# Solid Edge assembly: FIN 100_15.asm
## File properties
Title: Zylinder
Author: bmolnar
Template: iso assembly.asm
Last saved by: bmolnar
Revision: 6
Application: Solid Edge
Username: bmolnar
Dokumentum tartalom típus: 1
Document Number: FIN 100/15
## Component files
Kolbenstange.par
Profilrohr.par
Kit_1.par
Kit_2.par
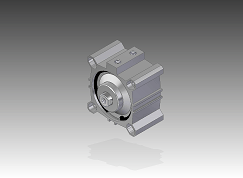
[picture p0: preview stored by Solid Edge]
